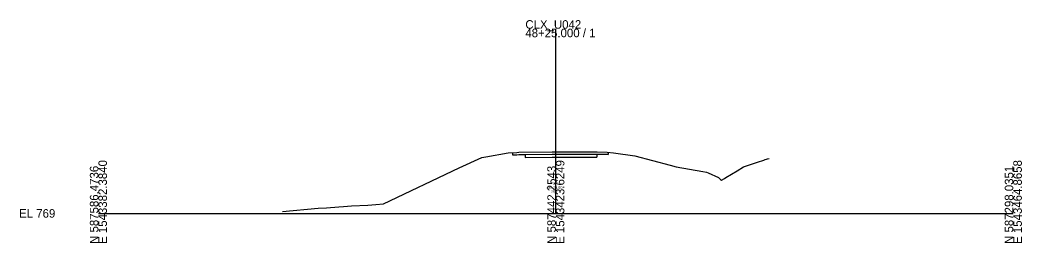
# Model space of a CAD drawing. Extents: x -26 to 1603, y -10 to 5557.
# Drawn here: x -25.7 to 302.8, y 4990.3 to 5063.4 of the extents above; entities that cross this region are included whole.
import ezdxf

# ---------------------------------------------------------------- set-up
doc = ezdxf.new("R2010")
doc.units = 0
for name, color, linetype in [('GK_Cells', 7, 'Continuous'), ('XS_P_Annotation', 7, 'Continuous'), ('XS_X_Ground_Line', 7, 'Continuous'), ('XS_X_Pavt', 7, 'Continuous')]:
    doc.layers.add(name, color=color, linetype=linetype)

msp = doc.modelspace()

# ---------------------------------------------------------------- linework, layer by layer
at = {"layer": 'GK_Cells'}
for p, q in [((150, 5000), (150, 5060.56)), ((0, 5000), (150, 5000)), ((150, 5000), (300, 5000))]:
    msp.add_line(p, q, dxfattribs=at)
at = {"layer": 'XS_X_Ground_Line'}
msp.add_lwpolyline([(60.34, 5000.64), (72.09, 5001.71), (74.76, 5001.83), (78.85, 5002.16), (80.37, 5002.26), (82.97, 5002.44), (88.3, 5002.67), (91.01, 5002.92), (93.5, 5003.14), (118.32, 5014.89), (125.69, 5018.38), (126.99, 5018.59), (134.4, 5019.85), (137.23, 5020), (137.9, 5020.03), (148.82, 5020.15), (150, 5020.17), (151.11, 5020.18), (151.6, 5020.18), (162.89, 5020.19), (163.55, 5020.18), (166.78, 5020.12), (168.95, 5019.82), (175.88, 5018.87), (187.46, 5015.83), (189.46, 5015.3), (198.2, 5013.75), (199.38, 5013.53), (199.99, 5013.25), (203.32, 5011.73), (203.96, 5011.17), (204.32, 5010.88), (205.27, 5011.44), (205.77, 5011.73), (209.45, 5014), (211.56, 5015.24), (213.51, 5015.9), (215.48, 5016.57), (216.73, 5016.99), (217.58, 5017.28), (218.2, 5017.49), (218.68, 5017.65), (219.05, 5017.78), (219.36, 5017.88), (219.95, 5018.05)], dxfattribs=at)
at = {"layer": 'XS_X_Pavt'}
for p, q in [((167.16, 5020.06), (167.16, 5019.31)), ((135.82, 5019.93), (135.82, 5019.18)), ((135.82, 5019.18), (137.23, 5019.25)), ((137.23, 5019.25), (137.9, 5019.28)), ((137.9, 5019.28), (139.95, 5019.3)), ((139.95, 5019.3), (148.82, 5019.4)), ((139.95, 5019.3), (139.95, 5018.3)), ((139.95, 5018.3), (148.82, 5018.4)), ((148.82, 5019.4), (150, 5019.42)), ((148.82, 5018.4), (150, 5018.42)), ((150, 5019.42), (151.11, 5019.43)), ((150, 5018.42), (151.11, 5018.43)), ((151.11, 5019.43), (151.6, 5019.43)), ((151.11, 5018.43), (151.6, 5018.43)), ((151.6, 5019.43), (162.89, 5019.44)), ((151.6, 5018.43), (162.89, 5018.44)), ((162.89, 5019.44), (163.41, 5019.43)), ((162.89, 5018.44), (163.41, 5018.43)), ((163.41, 5019.43), (163.55, 5019.43)), ((163.41, 5019.43), (163.41, 5018.43)), ((163.55, 5019.43), (166.78, 5019.37)), ((166.78, 5019.37), (167.16, 5019.31))]:
    msp.add_line(p, q, dxfattribs=at)

# ---------------------------------------------------------------- texts
at = {"layer": 'GK_Cells'}
for s, p in [('CLX_U042', (140, 5060.56)), ('48+25.000 / 1', (140, 5057.76)), ('EL 769', (-26, 4998.6))]:
    msp.add_text(s, height=2.8, dxfattribs=at).set_placement(p)
for s, p in [('E 1543382.3840', (2.8, 4990)), ('E 1543423.6249', (152.8, 4990)), ('E 1543464.8658', (302.8, 4990)), ('N 587586.4736', (0, 4990)), ('N 587442.2543', (150, 4990)), ('N 587298.0351', (300, 4990))]:
    msp.add_text(s, height=2.8, rotation=90, dxfattribs=at).set_placement(p)
at = {"layer": 'XS_P_Annotation'}
for s, height, p in [('789.17', 0.7, (148.42, 5009.55)), ('48+25.00', 0.9, (146.94, 5008.05)), ('789.17', 0.7, (148.42, 5006.75))]:
    msp.add_text(s, height=height, dxfattribs=at).set_placement(p)

doc.saveas('drawing.dxf')
